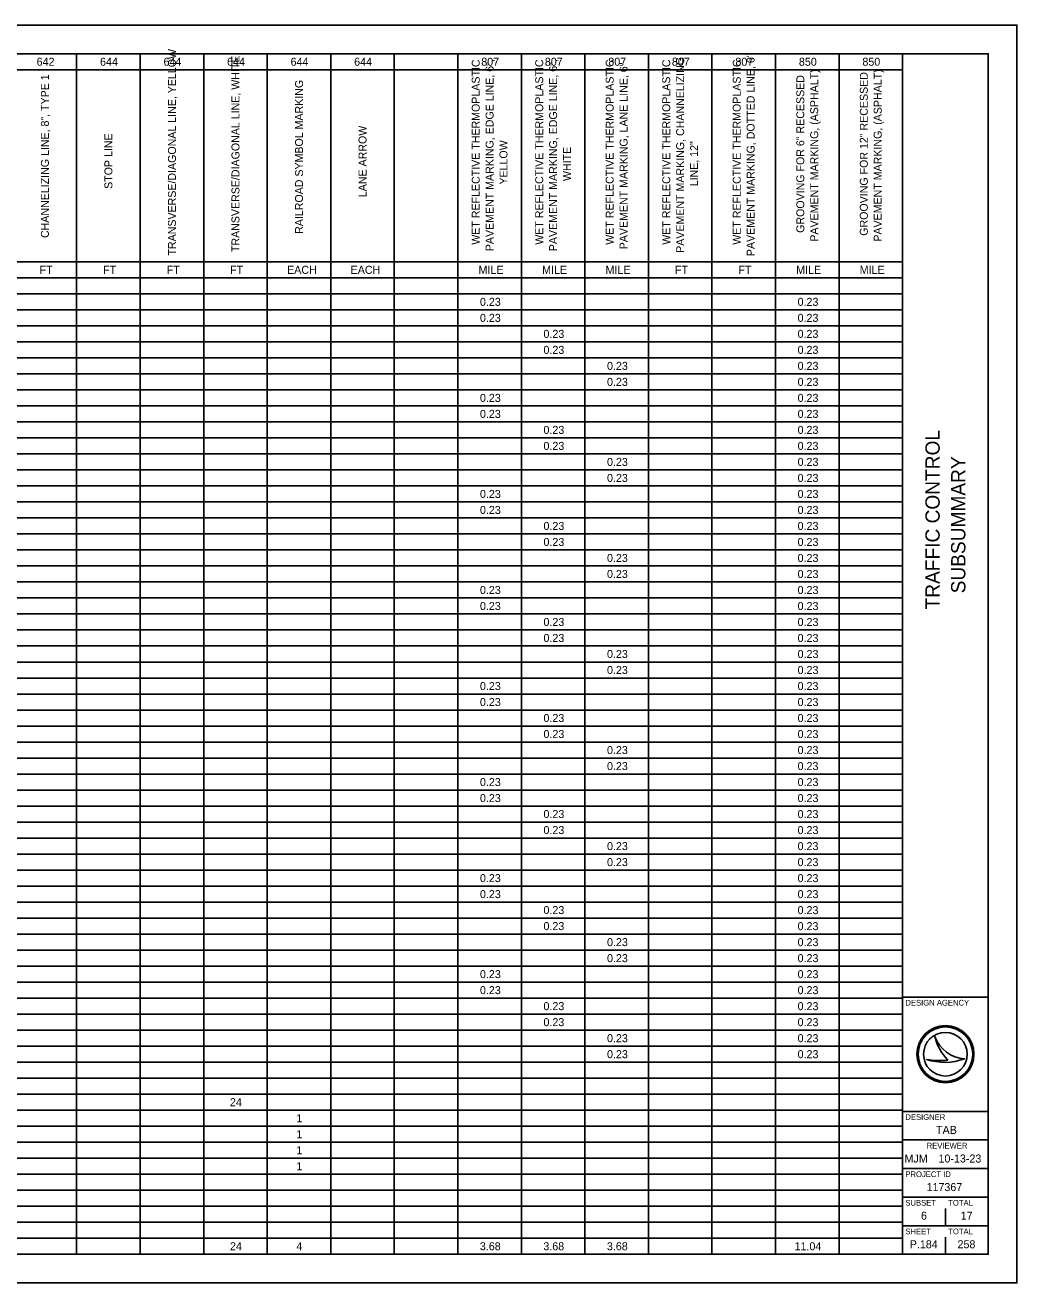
# Model space of a CAD drawing. Extents: x 0 to 34, y 0 to 22.
# Drawn here: x 16.65 to 34, y 0 to 22 of the extents above; entities that cross this region are included whole.
import ezdxf

# ---------------------------------------------------------------- set-up
doc = ezdxf.new("R2010")
doc.units = 0
for name, color, linetype in [('SH_Border', 7, 'Continuous'), ('SH_Cut_Line', 7, 'Continuous'), ('SH_Data', 7, 'Continuous'), ('SH_Text', 7, 'Continuous')]:
    doc.layers.add(name, color=color, linetype=linetype)

msp = doc.modelspace()

# ---------------------------------------------------------------- linework, layer by layer
at = {"layer": 'SH_Border'}
for p, q in [((32, 0.5), (32, 21.5)), ((32, 5), (33.5, 5)), ((32, 3), (33.5, 3)), ((32, 2.5), (33.5, 2.5)), ((32, 2), (33.5, 2)), ((32, 1.5), (33.5, 1.5)), ((32, 1), (33.5, 1))]:
    msp.add_line(p, q, dxfattribs=at)
msp.add_lwpolyline([(1.5, 21.5), (33.5, 21.5), (33.5, 0.5), (1.5, 0.5)], close=True, dxfattribs=at)
at = {"layer": 'SH_Cut_Line'}
msp.add_lwpolyline([(0, 0), (34, 0), (34, 22), (0, 22)], close=True, dxfattribs=at)
at = {"layer": 'SH_Data'}
for p, q in [((32.567, 4.31), (32.567, 4.31)), ((32.75, 4), (32.75, 4)), ((32.417, 3.91), (32.417, 3.91)), ((33.087, 3.919), (33.087, 3.919)), ((32.75, 1), (32.75, 1.3)), ((32.375, 0.675), (32.375, 0.675)), ((32.75, 0.5), (32.75, 0.8))]:
    msp.add_line(p, q, dxfattribs=at)
for radius in [0.5, 0.477, 0.477, 0.382]:
    msp.add_circle((32.75, 4), radius, dxfattribs=at)
for centre, radius, start, end in [((33.116, 4.498), 0.58, 198.9257, 198.9319), ((33.347, 4.47), 0.796, 191.6379, 191.6421), ((33.116, 4.498), 0.58, 198.9319, 267.1657), ((33.347, 4.47), 0.796, 191.6421, 226.0947), ((32.739, 4.87), 1.013, 251.4576, 290.0832), ((32.648, 5.154), 1.266, 259.4964, 259.4995), ((32.739, 4.87), 1.013, 251.4527, 251.4576), ((32.648, 5.154), 1.266, 259.4995, 276.6672)]:
    msp.add_arc(centre, radius, start, end, dxfattribs=at)
at = {"layer": 'SH_Text'}
for p, q in [((1.5, 21.5), (32, 21.5)), ((17.551, 21.5), (17.551, 0.5)), ((18.662, 21.5), (18.662, 0.5)), ((19.774, 21.5), (19.774, 0.5)), ((20.885, 21.5), (20.885, 0.5)), ((21.997, 21.5), (21.997, 0.5)), ((23.108, 21.5), (23.108, 0.5)), ((24.22, 21.5), (24.22, 0.5)), ((25.331, 21.5), (25.331, 0.5)), ((26.443, 21.5), (26.443, 0.5)), ((27.554, 21.5), (27.554, 0.5)), ((28.666, 21.5), (28.666, 0.5)), ((29.777, 21.5), (29.777, 0.5)), ((30.889, 21.5), (30.889, 0.5)), ((32, 21.5), (32, 0.5)), ((8.659, 21.22), (32, 21.22)), ((8.659, 17.86), (32, 17.86)), ((1.5, 17.58), (32, 17.58)), ((1.5, 17.3), (32, 17.3)), ((1.5, 17.02), (32, 17.02)), ((1.5, 16.74), (32, 16.74)), ((1.5, 16.46), (32, 16.46)), ((1.5, 16.18), (32, 16.18)), ((1.5, 15.9), (32, 15.9)), ((1.5, 15.62), (32, 15.62)), ((1.5, 15.34), (32, 15.34)), ((1.5, 15.06), (32, 15.06)), ((1.5, 14.78), (32, 14.78)), ((1.5, 14.5), (32, 14.5)), ((1.5, 14.22), (32, 14.22)), ((1.5, 13.94), (32, 13.94)), ((1.5, 13.66), (32, 13.66)), ((1.5, 13.38), (32, 13.38)), ((1.5, 13.1), (32, 13.1)), ((1.5, 12.82), (32, 12.82)), ((1.5, 12.54), (32, 12.54)), ((1.5, 12.26), (32, 12.26)), ((1.5, 11.98), (32, 11.98)), ((1.5, 11.7), (32, 11.7)), ((1.5, 11.42), (32, 11.42)), ((1.5, 11.14), (32, 11.14)), ((1.5, 10.86), (32, 10.86)), ((1.5, 10.58), (32, 10.58)), ((1.5, 10.3), (32, 10.3)), ((1.5, 10.02), (32, 10.02)), ((1.5, 9.74), (32, 9.74)), ((1.5, 9.46), (32, 9.46)), ((1.5, 9.18), (32, 9.18)), ((1.5, 8.9), (32, 8.9)), ((1.5, 8.62), (32, 8.62)), ((1.5, 8.34), (32, 8.34)), ((1.5, 8.06), (32, 8.06)), ((1.5, 7.78), (32, 7.78)), ((1.5, 7.5), (32, 7.5)), ((1.5, 7.22), (32, 7.22)), ((1.5, 6.94), (32, 6.94)), ((1.5, 6.66), (32, 6.66)), ((1.5, 6.38), (32, 6.38)), ((1.5, 6.1), (32, 6.1)), ((1.5, 5.82), (32, 5.82)), ((1.5, 5.54), (32, 5.54)), ((1.5, 5.26), (32, 5.26)), ((1.5, 4.98), (32, 4.98)), ((1.5, 4.7), (32, 4.7)), ((1.5, 4.42), (32, 4.42)), ((1.5, 4.14), (32, 4.14)), ((1.5, 3.86), (32, 3.86)), ((1.5, 3.58), (32, 3.58)), ((1.5, 3.3), (32, 3.3)), ((1.5, 3.02), (32, 3.02)), ((1.5, 2.74), (32, 2.74)), ((1.5, 2.46), (32, 2.46)), ((1.5, 2.18), (32, 2.18)), ((1.5, 1.9), (32, 1.9)), ((1.5, 1.62), (32, 1.62)), ((1.5, 1.34), (32, 1.34)), ((1.5, 1.06), (32, 1.06)), ((1.5, 0.78), (32, 0.78)), ((1.5, 0.5), (32, 0.5))]:
    msp.add_line(p, q, dxfattribs=at)

# ---------------------------------------------------------------- texts
at = {"layer": 'SH_Data'}
for s, p in [('TRAFFIC CONTROL', (32.65, 11.78)), ('SUBSUMMARY', (33.1, 12.061))]:
    msp.add_text(s, height=0.25, rotation=90, dxfattribs=at).set_placement(p)
for s, height, p in [('DESIGN AGENCY', 0.1, (32.05, 4.85)), ('DESIGNER', 0.1, (32.05, 2.85)), ('TAB', 0.14, (32.586, 2.605)), ('REVIEWER', 0.1, (32.422, 2.35)), ('MJM', 0.14, (32.035, 2.105)), ('10-13-23', 0.14, (32.629, 2.105)), ('PROJECT ID', 0.1, (32.05, 1.85)), ('117367', 0.14, (32.42, 1.605)), ('SUBSET', 0.1, (32.05, 1.35)), ('TOTAL', 0.1, (32.8, 1.35)), ('6', 0.14, (32.323, 1.105)), ('17', 0.14, (33.018, 1.105)), ('SHEET', 0.1, (32.05, 0.85)), ('TOTAL', 0.1, (32.8, 0.85)), ('P.184', 0.14, (32.126, 0.605)), ('258', 0.14, (32.962, 0.605))]:
    msp.add_text(s, height=height, dxfattribs=at).set_placement(p)
at = {"layer": 'SH_Text'}
for s, height, p in [('TRANSVERSE/DIAGONAL LINE, YELLOW', 0.13893, (19.288, 17.97)), ('TRANSVERSE/DIAGONAL LINE, WHITE', 0.13893, (20.399, 18.031)), ('WET REFLECTIVE THERMOPLASTIC ', 0.13893, (24.602, 18.159)), ('PAVEMENT MARKING, EDGE LINE, 6", ', 0.13893, (24.845, 18.046)), ('WET REFLECTIVE THERMOPLASTIC ', 0.13893, (25.713, 18.159)), ('PAVEMENT MARKING, EDGE LINE, 6", ', 0.13893, (25.956, 18.046)), ('WET REFLECTIVE THERMOPLASTIC ', 0.13893, (26.946, 18.159)), ('WET REFLECTIVE THERMOPLASTIC ', 0.13893, (27.936, 18.159)), ('PAVEMENT MARKING, CHANNELIZING ', 0.13893, (28.179, 18.017)), ('WET REFLECTIVE THERMOPLASTIC ', 0.13893, (29.169, 18.159)), ('PAVEMENT MARKING, DOTTED LINE, 6"', 0.13893, (29.412, 17.96)), ('CHANNELIZING LINE, 8", TYPE 1', 0.13893, (17.065, 18.276)), ('PAVEMENT MARKING, LANE LINE, 6"', 0.13893, (27.189, 18.08)), ('PAVEMENT MARKING, (ASPHALT)', 0.13893, (30.524, 18.213)), ('GROOVING FOR 12" RECESSED ', 0.13893, (31.392, 18.316)), ('PAVEMENT MARKING, (ASPHALT)', 0.13893, (31.635, 18.213)), ('RAILROAD SYMBOL MARKING', 0.13893, (21.511, 18.349)), ('GROOVING FOR 6" RECESSED ', 0.13893, (30.281, 18.367)), ('LANE ARROW', 0.1389, (22.622, 18.992)), ('STOP LINE', 0.1389, (18.176, 19.136)), ('YELLOW', 0.1389, (25.088, 19.212)), ('WHITE', 0.1389, (26.2, 19.273)), ('LINE, 12"', 0.1389, (28.422, 19.181))]:
    msp.add_text(s, height=height, rotation=90, dxfattribs=at).set_placement(p)
for s, p in [('642', (16.851, 21.29)), ('644', (17.96, 21.29)), ('644', (19.071, 21.29)), ('644', (20.183, 21.29)), ('644', (21.294, 21.29)), ('644', (22.406, 21.29)), ('807', (24.63, 21.29)), ('807', (25.742, 21.29)), ('807', (26.853, 21.29)), ('807', (27.965, 21.29)), ('807', (29.076, 21.29)), ('850', (30.187, 21.29)), ('850', (31.298, 21.29)), ('FT', (16.903, 17.65)), ('FT', (18.014, 17.65)), ('FT', (19.126, 17.65)), ('FT', (20.237, 17.65)), ('EACH', (21.232, 17.65)), ('EACH', (22.344, 17.65)), ('MILE', (24.582, 17.65)), ('MILE', (25.694, 17.65)), ('MILE', (26.805, 17.65)), ('FT', (28.017, 17.65)), ('FT', (29.129, 17.65)), ('MILE', (30.139, 17.65)), ('MILE', (31.251, 17.65)), ('0.23', (24.607, 17.09)), ('0.23', (30.164, 17.09)), ('0.23', (24.607, 16.81)), ('0.23', (30.164, 16.81)), ('0.23', (25.718, 16.53)), ('0.23', (30.164, 16.53)), ('0.23', (25.718, 16.25)), ('0.23', (30.164, 16.25)), ('0.23', (26.83, 15.97)), ('0.23', (30.164, 15.97)), ('0.23', (26.83, 15.69)), ('0.23', (30.164, 15.69)), ('0.23', (24.607, 15.41)), ('0.23', (30.164, 15.41)), ('0.23', (24.607, 15.13)), ('0.23', (30.164, 15.13)), ('0.23', (25.718, 14.85)), ('0.23', (30.164, 14.85)), ('0.23', (25.718, 14.57)), ('0.23', (30.164, 14.57)), ('0.23', (26.83, 14.29)), ('0.23', (30.164, 14.29)), ('0.23', (26.83, 14.01)), ('0.23', (30.164, 14.01)), ('0.23', (24.607, 13.73)), ('0.23', (30.164, 13.73)), ('0.23', (24.607, 13.45)), ('0.23', (30.164, 13.45)), ('0.23', (25.718, 13.17)), ('0.23', (30.164, 13.17)), ('0.23', (25.718, 12.89)), ('0.23', (30.164, 12.89)), ('0.23', (26.83, 12.61)), ('0.23', (30.164, 12.61)), ('0.23', (26.83, 12.33)), ('0.23', (30.164, 12.33)), ('0.23', (24.607, 12.05)), ('0.23', (30.164, 12.05)), ('0.23', (24.607, 11.77)), ('0.23', (30.164, 11.77)), ('0.23', (25.718, 11.49)), ('0.23', (30.164, 11.49)), ('0.23', (25.718, 11.21)), ('0.23', (30.164, 11.21)), ('0.23', (26.83, 10.93)), ('0.23', (30.164, 10.93)), ('0.23', (26.83, 10.65)), ('0.23', (30.164, 10.65)), ('0.23', (24.607, 10.37)), ('0.23', (30.164, 10.37)), ('0.23', (24.607, 10.09)), ('0.23', (30.164, 10.09)), ('0.23', (25.718, 9.81)), ('0.23', (30.164, 9.81)), ('0.23', (25.718, 9.53)), ('0.23', (30.164, 9.53)), ('0.23', (26.83, 9.25)), ('0.23', (30.164, 9.25)), ('0.23', (26.83, 8.97)), ('0.23', (30.164, 8.97)), ('0.23', (24.607, 8.69)), ('0.23', (30.164, 8.69)), ('0.23', (24.607, 8.41)), ('0.23', (30.164, 8.41)), ('0.23', (25.718, 8.13)), ('0.23', (30.164, 8.13)), ('0.23', (25.718, 7.85)), ('0.23', (30.164, 7.85)), ('0.23', (26.83, 7.57)), ('0.23', (30.164, 7.57)), ('0.23', (26.83, 7.29)), ('0.23', (30.164, 7.29)), ('0.23', (24.607, 7.01)), ('0.23', (30.164, 7.01)), ('0.23', (24.607, 6.73)), ('0.23', (30.164, 6.73)), ('0.23', (25.718, 6.45)), ('0.23', (30.164, 6.45)), ('0.23', (25.718, 6.17)), ('0.23', (30.164, 6.17)), ('0.23', (26.83, 5.89)), ('0.23', (30.164, 5.89)), ('0.23', (26.83, 5.61)), ('0.23', (30.164, 5.61)), ('0.23', (24.607, 5.33)), ('0.23', (30.164, 5.33)), ('0.23', (24.607, 5.05)), ('0.23', (30.164, 5.05)), ('0.23', (25.718, 4.77)), ('0.23', (30.164, 4.77)), ('0.23', (25.718, 4.49)), ('0.23', (30.164, 4.49)), ('0.23', (26.83, 4.21)), ('0.23', (30.164, 4.21)), ('0.23', (26.83, 3.93)), ('0.23', (30.164, 3.93)), ('24', (20.233, 3.09)), ('1', (21.396, 2.81)), ('1', (21.396, 2.53)), ('1', (21.396, 2.25)), ('1', (21.396, 1.97)), ('24', (20.233, 0.57)), ('4', (21.394, 0.57)), ('3.68', (24.605, 0.57)), ('3.68', (25.716, 0.57)), ('3.68', (26.828, 0.57)), ('11.04', (30.111, 0.57))]:
    msp.add_text(s, height=0.14, dxfattribs=at).set_placement(p)

doc.saveas('drawing.dxf')
